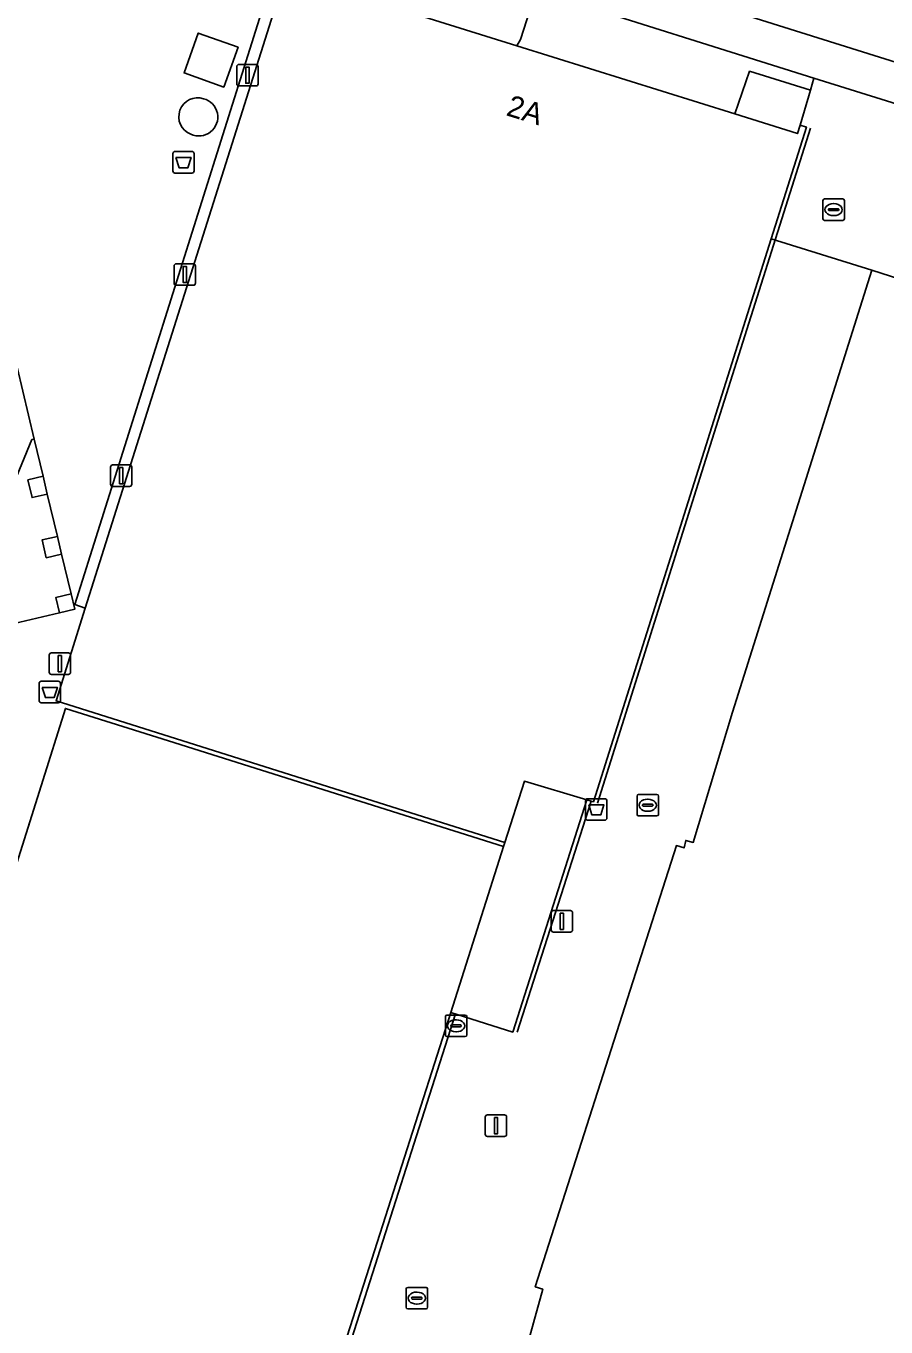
# Model space of a CAD drawing. Extents: x 160675 to 161153, y 383241 to 383714.
# Drawn here: x 161053 to 161093, y 383407.9 to 383468.4 of the extents above; entities that cross this region are included whole.
import ezdxf

# ---------------------------------------------------------------- set-up
doc = ezdxf.new("R2010")
doc.units = 0
for name, color, linetype in [('IMGEO_Afvalbak', 7, 'Continuous'), ('IMGEO_Fietspad_gesloten', 7, 'Continuous'), ('IMGEO_Grasland_overig', 7, 'Continuous'), ('IMGEO_Kolk', 7, 'Continuous'), ('IMGEO_Lichtmast', 7, 'Continuous'), ('IMGEO_Lijnafwatering', 7, 'Continuous'), ('IMGEO_Pand', 7, 'Continuous'), ('IMGEO_Pand_nummerreeks', 7, 'Continuous'), ('IMGEO_Pand_overbouw', 7, 'Continuous'), ('IMGEO_Rijbaan_lokaal_open', 7, 'Continuous'), ('IMGEO_Rioolput', 7, 'Continuous'), ('IMGEO_Terreindeel_open', 7, 'Continuous'), ('IMGEO_Voetgangersgebied_open', 7, 'Continuous'), ('IMGEO_Voetpad_gesloten', 7, 'Continuous'), ('IMGEO_Voetpad_open', 7, 'Continuous')]:
    doc.layers.add(name, color=color, linetype=linetype)

msp = doc.modelspace()

# ---------------------------------------------------------------- linework, layer by layer
at = {"layer": 'IMGEO_Afvalbak'}
for p, q in [((161059.823, 383461.628), (161059.823, 383462.428)), ((161059.823, 383462.428), (161059.823, 383461.628)), ((161059.923, 383462.528), (161060.713, 383462.528)), ((161060.713, 383462.528), (161059.923, 383462.528)), ((161060.813, 383462.428), (161060.813, 383461.628)), ((161060.813, 383461.628), (161060.813, 383462.428)), ((161060.713, 383461.528), (161059.923, 383461.528)), ((161059.923, 383461.528), (161060.713, 383461.528)), ((161053.609, 383436.998), (161053.609, 383437.798)), ((161053.609, 383437.798), (161053.609, 383436.998)), ((161053.709, 383437.898), (161054.499, 383437.898)), ((161054.499, 383437.898), (161053.709, 383437.898)), ((161054.599, 383437.798), (161054.599, 383436.998)), ((161054.599, 383436.998), (161054.599, 383437.798)), ((161054.499, 383436.898), (161053.709, 383436.898)), ((161053.709, 383436.898), (161054.499, 383436.898)), ((161079.007, 383431.541), (161079.007, 383432.341)), ((161079.007, 383432.341), (161079.007, 383431.541)), ((161079.107, 383432.441), (161079.897, 383432.441)), ((161079.897, 383432.441), (161079.107, 383432.441)), ((161079.997, 383432.341), (161079.997, 383431.541)), ((161079.997, 383431.541), (161079.997, 383432.341)), ((161079.897, 383431.441), (161079.107, 383431.441)), ((161079.107, 383431.441), (161079.897, 383431.441))]:
    msp.add_line(p, q, dxfattribs=at)
for points in [[(161059.966, 383462.242), (161060.67, 383462.242), (161060.521, 383461.772), (161060.115, 383461.772), (161059.966, 383462.242)], [(161053.752, 383437.612), (161054.456, 383437.612), (161054.307, 383437.142), (161053.901, 383437.142), (161053.752, 383437.612)], [(161079.15, 383432.155), (161079.854, 383432.155), (161079.705, 383431.685), (161079.299, 383431.685), (161079.15, 383432.155)]]:
    msp.add_lwpolyline(points, dxfattribs=at)
for centre, start, end in [((161059.923, 383462.428), 90, 180), ((161059.923, 383462.428), 90, 180), ((161060.713, 383462.428), 0, 90), ((161060.713, 383462.428), 360, 90), ((161059.923, 383461.628), 180, 270), ((161059.923, 383461.628), 180, 270), ((161060.713, 383461.628), 270, 0), ((161060.713, 383461.628), 270, 0), ((161053.709, 383437.798), 90, 180), ((161053.709, 383437.798), 90, 180), ((161054.499, 383437.798), 0, 90), ((161054.499, 383437.798), 360, 90), ((161053.709, 383436.998), 180, 270), ((161053.709, 383436.998), 180, 270), ((161054.499, 383436.998), 270, 0), ((161054.499, 383436.998), 270, 0), ((161079.107, 383432.341), 90, 180), ((161079.107, 383432.341), 90, 180), ((161079.897, 383432.341), 0, 90), ((161079.897, 383432.341), 360, 90), ((161079.107, 383431.541), 180, 270), ((161079.107, 383431.541), 180, 270), ((161079.897, 383431.541), 270, 0), ((161079.897, 383431.541), 270, 0)]:
    msp.add_arc(centre, 0.1, start, end, dxfattribs=at)
at = {"layer": 'IMGEO_Fietspad_gesloten'}
msp.add_lwpolyline([(161117.721, 383459.056), (161117.222, 383459.213), (161077.255, 383471.761), (161076.702, 383470.014), (161089.617, 383465.938), (161116.681, 383457.491), (161117.138, 383457.349)], dxfattribs=at)
msp.add_lwpolyline([(161089.617, 383465.938), (161076.702, 383470.014), (161075.979, 383467.73), (161075.812, 383467.442), (161085.936, 383464.272), (161086.624, 383466.255), (161089.451, 383465.38)], close=True, dxfattribs=at)
at = {"layer": 'IMGEO_Grasland_overig'}
msp.add_lwpolyline([(161065.07, 383470.806), (161064.564, 383470.995), (161055.274, 383441.468), (161055.753, 383441.293)], close=True, dxfattribs=at)
at = {"layer": 'IMGEO_Kolk'}
for p, q in [((161072.487, 383421.458), (161072.487, 383422.31)), ((161072.562, 383422.384), (161073.414, 383422.384)), ((161072.975, 383422.164), (161073, 383422.164)), ((161073.488, 383422.31), (161073.488, 383421.458)), ((161072.746, 383421.878), (161072.746, 383421.89)), ((161073.184, 383421.841), (161072.786, 383421.841)), ((161072.789, 383421.927), (161073.187, 383421.927)), ((161072.998, 383421.604), (161072.973, 383421.604)), ((161073.23, 383421.89), (161073.23, 383421.878)), ((161073.414, 383421.384), (161072.562, 383421.384))]:
    msp.add_line(p, q, dxfattribs=at)
for points in [[(161072.487, 383421.458), (161072.487, 383422.31)], [(161072.562, 383422.384), (161073.414, 383422.384)], [(161073.488, 383422.31), (161073.488, 383421.458)], [(161073.414, 383421.384), (161072.562, 383421.384)]]:
    msp.add_lwpolyline(points, dxfattribs=at)
for centre, radius, start, end in [((161072.564, 383422.308), 0.0765, 91.55205, 178.44795), ((161072.564, 383422.308), 0.0765, 91.55205, 178.44795), ((161073.412, 383422.308), 0.0765, 1.55205, 88.44795), ((161073.412, 383422.308), 0.0765, 1.55205, 88.44795), ((161072.564, 383421.46), 0.0765, 181.55205, 268.44795), ((161072.564, 383421.46), 0.0765, 181.55205, 268.44795), ((161072.786, 383421.887), 0.0403, 85.87752, 175.75265), ((161072.783, 383421.877), 0.0366, 178.93798, 274.71019), ((161073.187, 383421.884), 0.043, 264.86636, 352.45326), ((161073.191, 383421.889), 0.0386, 1.73085, 96.63898), ((161073.412, 383421.46), 0.0765, 271.55205, 358.44795), ((161073.412, 383421.46), 0.0765, 271.55205, 358.44795)]:
    msp.add_arc(centre, radius, start, end, dxfattribs=at)
for centre, major_axis, ratio, start_param, end_param in [((161072.974, 383421.884), (-0.387, 0.002), 0.722429, 4.712389, 7.853982), ((161072.999, 383421.884), (-0.39, 0.002), 0.717154, 1.570796, 4.712389)]:
    msp.add_ellipse(centre, major_axis=major_axis, ratio=ratio, start_param=start_param, end_param=end_param, dxfattribs=at)
at = {"layer": 'IMGEO_Lichtmast'}
for p, q in [((161062.794, 383465.673), (161062.794, 383466.473)), ((161062.794, 383466.473), (161062.794, 383465.673)), ((161062.894, 383466.573), (161063.684, 383466.573)), ((161063.684, 383466.573), (161062.894, 383466.573)), ((161063.784, 383466.473), (161063.784, 383465.673)), ((161063.784, 383465.673), (161063.784, 383466.473)), ((161063.684, 383465.573), (161062.894, 383465.573)), ((161062.894, 383465.573), (161063.684, 383465.573)), ((161059.883, 383456.407), (161059.883, 383457.207)), ((161059.883, 383457.207), (161059.883, 383456.407)), ((161059.983, 383457.307), (161060.773, 383457.307)), ((161060.773, 383457.307), (161059.983, 383457.307)), ((161060.873, 383457.207), (161060.873, 383456.407)), ((161060.873, 383456.407), (161060.873, 383457.207)), ((161060.773, 383456.307), (161059.983, 383456.307)), ((161059.983, 383456.307), (161060.773, 383456.307)), ((161056.926, 383447.056), (161056.926, 383447.856)), ((161056.926, 383447.856), (161056.926, 383447.056)), ((161057.026, 383447.956), (161057.816, 383447.956)), ((161057.816, 383447.956), (161057.026, 383447.956)), ((161057.916, 383447.856), (161057.916, 383447.056)), ((161057.916, 383447.056), (161057.916, 383447.856)), ((161057.816, 383446.956), (161057.026, 383446.956)), ((161057.026, 383446.956), (161057.816, 383446.956)), ((161054.078, 383438.318), (161054.078, 383439.118)), ((161054.078, 383439.118), (161054.078, 383438.318)), ((161054.178, 383439.218), (161054.968, 383439.218)), ((161054.968, 383439.218), (161054.178, 383439.218)), ((161055.068, 383439.118), (161055.068, 383438.318)), ((161055.068, 383438.318), (161055.068, 383439.118)), ((161054.968, 383438.218), (161054.178, 383438.218)), ((161054.178, 383438.218), (161054.968, 383438.218)), ((161077.406, 383426.343), (161077.406, 383427.143)), ((161077.406, 383427.143), (161077.406, 383426.343)), ((161077.506, 383427.243), (161078.296, 383427.243)), ((161078.296, 383427.243), (161077.506, 383427.243)), ((161078.396, 383427.143), (161078.396, 383426.343)), ((161078.396, 383426.343), (161078.396, 383427.143)), ((161078.296, 383426.243), (161077.506, 383426.243)), ((161077.506, 383426.243), (161078.296, 383426.243)), ((161074.345, 383416.84), (161074.345, 383417.64)), ((161074.345, 383417.64), (161074.345, 383416.84)), ((161074.445, 383417.74), (161075.235, 383417.74)), ((161075.235, 383417.74), (161074.445, 383417.74)), ((161075.335, 383417.64), (161075.335, 383416.84)), ((161075.335, 383416.84), (161075.335, 383417.64)), ((161075.235, 383416.74), (161074.445, 383416.74)), ((161074.445, 383416.74), (161075.235, 383416.74))]:
    msp.add_line(p, q, dxfattribs=at)
for points in [[(161063.214, 383466.448), (161063.364, 383466.448), (161063.364, 383465.698), (161063.214, 383465.698), (161063.214, 383466.448)], [(161060.303, 383457.182), (161060.453, 383457.182), (161060.453, 383456.432), (161060.303, 383456.432), (161060.303, 383457.182)], [(161057.346, 383447.831), (161057.496, 383447.831), (161057.496, 383447.081), (161057.346, 383447.081), (161057.346, 383447.831)], [(161054.498, 383439.093), (161054.648, 383439.093), (161054.648, 383438.343), (161054.498, 383438.343), (161054.498, 383439.093)], [(161077.826, 383427.118), (161077.976, 383427.118), (161077.976, 383426.368), (161077.826, 383426.368), (161077.826, 383427.118)], [(161074.765, 383417.615), (161074.915, 383417.615), (161074.915, 383416.865), (161074.765, 383416.865), (161074.765, 383417.615)]]:
    msp.add_lwpolyline(points, dxfattribs=at)
for centre, start, end in [((161062.894, 383466.473), 90, 180), ((161062.894, 383466.473), 90, 180), ((161063.684, 383466.473), 0, 90), ((161063.684, 383466.473), 360, 90), ((161062.894, 383465.673), 180, 270), ((161062.894, 383465.673), 180, 270), ((161063.684, 383465.673), 270, 0), ((161063.684, 383465.673), 270, 0), ((161059.983, 383457.207), 90, 180), ((161059.983, 383457.207), 90, 180), ((161060.773, 383457.207), 0, 90), ((161060.773, 383457.207), 360, 90), ((161059.983, 383456.407), 180, 270), ((161059.983, 383456.407), 180, 270), ((161060.773, 383456.407), 270, 0), ((161060.773, 383456.407), 270, 0), ((161057.026, 383447.856), 90, 180), ((161057.026, 383447.856), 90, 180), ((161057.816, 383447.856), 0, 90), ((161057.816, 383447.856), 360, 90), ((161057.026, 383447.056), 180, 270), ((161057.026, 383447.056), 180, 270), ((161057.816, 383447.056), 270, 0), ((161057.816, 383447.056), 270, 0), ((161054.178, 383439.118), 90, 180), ((161054.178, 383439.118), 90, 180), ((161054.968, 383439.118), 0, 90), ((161054.968, 383439.118), 360, 90), ((161054.178, 383438.318), 180, 270), ((161054.178, 383438.318), 180, 270), ((161054.968, 383438.318), 270, 0), ((161054.968, 383438.318), 270, 0), ((161077.506, 383427.143), 90, 180), ((161077.506, 383427.143), 90, 180), ((161078.296, 383427.143), 0, 90), ((161078.296, 383427.143), 360, 90), ((161077.506, 383426.343), 180, 270), ((161077.506, 383426.343), 180, 270), ((161078.296, 383426.343), 270, 0), ((161078.296, 383426.343), 270, 0), ((161074.445, 383417.64), 90, 180), ((161074.445, 383417.64), 90, 180), ((161075.235, 383417.64), 0, 90), ((161075.235, 383417.64), 360, 90), ((161074.445, 383416.84), 180, 270), ((161074.445, 383416.84), 180, 270), ((161075.235, 383416.84), 270, 0), ((161075.235, 383416.84), 270, 0)]:
    msp.add_arc(centre, 0.1, start, end, dxfattribs=at)
at = {"layer": 'IMGEO_Lijnafwatering'}
for points in [[(161084.506, 383447.923), (161089.456, 383463.605)], [(161079.556, 383432.24), (161084.506, 383447.923)], [(161059.617, 383435.13), (161054.833, 383436.641), (161051.429, 383425.846)], [(161075.195, 383430.212), (161059.617, 383435.13)], [(161075.832, 383421.583), (161079.256, 383432.332)], [(161066.777, 383403.1), (161068.012, 383406.968), (161072.955, 383422.439)]]:
    msp.add_lwpolyline(points, dxfattribs=at)
at = {"layer": 'IMGEO_Pand'}
for points in [[(161087.625, 383458.471), (161089.265, 383463.665), (161088.969, 383463.756), (161088.845, 383463.361), (161085.936, 383464.272), (161075.812, 383467.442), (161065.769, 383470.587), (161065.355, 383470.717), (161065.07, 383470.806), (161055.753, 383441.293), (161054.395, 383436.989), (161054.702, 383436.892), (161075.255, 383430.401), (161076.159, 383433.252), (161079.064, 383432.389), (161079.256, 383432.332), (161079.365, 383432.3)], [(161053.796, 383447.429), (161053.086, 383447.264), (161053.279, 383446.436), (161053.989, 383446.602)], [(161054.457, 383444.637), (161053.75, 383444.473), (161053.943, 383443.64), (161054.651, 383443.805)], [(161055.101, 383441.964), (161054.39, 383441.801), (161054.553, 383441.089), (161055.264, 383441.251)]]:
    msp.add_lwpolyline(points, close=True, dxfattribs=at)
for points in [[(161099.585, 383454.678), (161092.303, 383457.008), (161085.837, 383436.463), (161084.008, 383430.41), (161083.662, 383430.505), (161083.581, 383430.155), (161083.222, 383430.26), (161076.661, 383409.753), (161077.013, 383409.636), (161075.201, 383403.108)], [(161049.507, 383440.018), (161053.275, 383449.133), (161053.38, 383449.156), (161051.779, 383455.847)]]:
    msp.add_lwpolyline(points, dxfattribs=at)
at = {"layer": 'IMGEO_Pand_overbouw'}
msp.add_lwpolyline([(161055.101, 383441.964), (161054.651, 383443.805), (161053.943, 383443.64), (161053.75, 383444.473), (161054.457, 383444.637), (161053.989, 383446.602), (161053.279, 383446.436), (161053.086, 383447.264), (161053.796, 383447.429), (161053.38, 383449.156), (161053.275, 383449.133), (161049.507, 383440.018), (161049.535, 383439.901), (161054.553, 383441.089), (161054.39, 383441.801)], close=True, dxfattribs=at)
at = {"layer": 'IMGEO_Rijbaan_lokaal_open'}
msp.add_lwpolyline([(161066.803, 383474.038), (161066.557, 383473.216), (161076.702, 383470.014), (161077.255, 383471.761), (161117.222, 383459.213), (161117.721, 383459.056)], dxfattribs=at)
msp.add_lwpolyline([(161075.812, 383467.442), (161075.979, 383467.73), (161076.702, 383470.014), (161066.557, 383473.216), (161065.997, 383471.348), (161065.769, 383470.587)], close=True, dxfattribs=at)
at = {"layer": 'IMGEO_Rioolput'}
for p, q in [((161090.03, 383459.399), (161090.03, 383460.251)), ((161090.105, 383460.325), (161090.957, 383460.325)), ((161091.031, 383460.251), (161091.031, 383459.399)), ((161090.289, 383459.819), (161090.289, 383459.831)), ((161090.727, 383459.782), (161090.329, 383459.782)), ((161090.332, 383459.868), (161090.73, 383459.868)), ((161090.541, 383459.545), (161090.516, 383459.545)), ((161090.518, 383460.105), (161090.543, 383460.105)), ((161090.773, 383459.831), (161090.773, 383459.819)), ((161090.957, 383459.325), (161090.105, 383459.325)), ((161081.394, 383431.712), (161081.394, 383432.564)), ((161081.469, 383432.638), (161082.321, 383432.638)), ((161081.882, 383432.418), (161081.907, 383432.418)), ((161082.395, 383432.564), (161082.395, 383431.712)), ((161081.653, 383432.132), (161081.653, 383432.144)), ((161082.091, 383432.095), (161081.693, 383432.095)), ((161081.696, 383432.181), (161082.094, 383432.181)), ((161081.905, 383431.858), (161081.88, 383431.858)), ((161082.137, 383432.144), (161082.137, 383432.132)), ((161082.321, 383431.638), (161081.469, 383431.638)), ((161070.661, 383408.798), (161070.661, 383409.65)), ((161070.736, 383409.724), (161071.588, 383409.724)), ((161071.149, 383409.504), (161071.174, 383409.504)), ((161071.662, 383409.65), (161071.662, 383408.798)), ((161071.588, 383408.724), (161070.736, 383408.724)), ((161070.92, 383409.218), (161070.92, 383409.23)), ((161071.358, 383409.181), (161070.96, 383409.181)), ((161070.963, 383409.267), (161071.361, 383409.267)), ((161071.172, 383408.944), (161071.147, 383408.944)), ((161071.404, 383409.23), (161071.404, 383409.218))]:
    msp.add_line(p, q, dxfattribs=at)
for points in [[(161090.03, 383459.399), (161090.03, 383460.251)], [(161090.105, 383460.325), (161090.957, 383460.325)], [(161091.031, 383460.251), (161091.031, 383459.399)], [(161090.957, 383459.325), (161090.105, 383459.325)], [(161081.394, 383431.712), (161081.394, 383432.564)], [(161081.469, 383432.638), (161082.321, 383432.638)], [(161082.395, 383432.564), (161082.395, 383431.712)], [(161082.321, 383431.638), (161081.469, 383431.638)], [(161070.661, 383408.798), (161070.661, 383409.65)], [(161070.736, 383409.724), (161071.588, 383409.724)], [(161071.662, 383409.65), (161071.662, 383408.798)], [(161071.588, 383408.724), (161070.736, 383408.724)]]:
    msp.add_lwpolyline(points, dxfattribs=at)
for centre, radius, start, end in [((161090.107, 383460.249), 0.0765, 91.55205, 178.44795), ((161090.107, 383460.249), 0.0765, 91.55205, 178.44795), ((161090.955, 383460.249), 0.0765, 1.55205, 88.44795), ((161090.955, 383460.249), 0.0765, 1.55205, 88.44795), ((161090.329, 383459.828), 0.0403, 85.87752, 175.75265), ((161090.326, 383459.818), 0.0366, 178.93798, 274.71019), ((161090.73, 383459.825), 0.043, 264.86636, 352.45326), ((161090.734, 383459.83), 0.0386, 1.73085, 96.63898), ((161090.107, 383459.401), 0.0765, 181.55205, 268.44795), ((161090.107, 383459.401), 0.0765, 181.55205, 268.44795), ((161090.955, 383459.401), 0.0765, 271.55205, 358.44795), ((161090.955, 383459.401), 0.0765, 271.55205, 358.44795), ((161081.471, 383432.562), 0.0765, 91.55205, 178.44795), ((161081.471, 383432.562), 0.0765, 91.55205, 178.44795), ((161082.319, 383432.562), 0.0765, 1.55205, 88.44795), ((161082.319, 383432.562), 0.0765, 1.55205, 88.44795), ((161081.471, 383431.714), 0.0765, 181.55205, 268.44795), ((161081.471, 383431.714), 0.0765, 181.55205, 268.44795), ((161081.693, 383432.141), 0.0403, 85.87752, 175.75265), ((161081.69, 383432.131), 0.0366, 178.93798, 274.71019), ((161082.094, 383432.138), 0.043, 264.86636, 352.45326), ((161082.098, 383432.143), 0.0386, 1.73085, 96.63898), ((161082.319, 383431.714), 0.0765, 271.55205, 358.44795), ((161082.319, 383431.714), 0.0765, 271.55205, 358.44795), ((161070.738, 383409.648), 0.0765, 91.55205, 178.44795), ((161070.738, 383409.648), 0.0765, 91.55205, 178.44795), ((161071.586, 383409.648), 0.0765, 1.55205, 88.44795), ((161071.586, 383409.648), 0.0765, 1.55205, 88.44795), ((161070.738, 383408.8), 0.0765, 181.55205, 268.44795), ((161070.738, 383408.8), 0.0765, 181.55205, 268.44795), ((161070.96, 383409.227), 0.0403, 85.87752, 175.75265), ((161070.957, 383409.217), 0.0366, 178.93798, 274.71019), ((161071.361, 383409.224), 0.043, 264.86636, 352.45326), ((161071.365, 383409.229), 0.0386, 1.73085, 96.63898), ((161071.586, 383408.8), 0.0765, 271.55205, 358.44795), ((161071.586, 383408.8), 0.0765, 271.55205, 358.44795)]:
    msp.add_arc(centre, radius, start, end, dxfattribs=at)
for centre, major_axis, ratio, start_param, end_param in [((161090.517, 383459.825), (-0.387, 0.002), 0.722429, 4.712389, 7.853982), ((161090.542, 383459.825), (-0.39, 0.002), 0.717154, 1.570796, 4.712389), ((161081.881, 383432.138), (-0.387, 0.002), 0.722429, 4.712389, 7.853982), ((161081.906, 383432.138), (-0.39, 0.002), 0.717154, 1.570796, 4.712389), ((161071.148, 383409.224), (-0.387, 0.002), 0.722429, 4.712389, 7.853982), ((161071.173, 383409.224), (-0.39, 0.002), 0.717154, 1.570796, 4.712389)]:
    msp.add_ellipse(centre, major_axis=major_axis, ratio=ratio, start_param=start_param, end_param=end_param, dxfattribs=at)
at = {"layer": 'IMGEO_Terreindeel_open'}
msp.add_lwpolyline([(161062.192, 383465.522), (161062.855, 383467.373), (161061.005, 383468.035), (161060.342, 383466.184)], close=True, dxfattribs=at)
for centre, radius, start, end in [((161060.977, 383464.148), 0.877, 71.68188, 248.36866), ((161061.03, 383464.129), 0.881, 244.68747, 75.36307)]:
    msp.add_arc(centre, radius, start, end, dxfattribs=at)
at = {"layer": 'IMGEO_Voetgangersgebied_open'}
for points in [[(161116.681, 383457.491), (161089.617, 383465.938), (161089.451, 383465.38), (161088.969, 383463.756), (161089.265, 383463.665), (161087.625, 383458.471), (161092.303, 383457.008), (161099.585, 383454.678)], [(161075.201, 383403.108), (161077.013, 383409.636), (161076.661, 383409.753), (161083.222, 383430.26), (161083.581, 383430.155), (161083.662, 383430.505), (161084.008, 383430.41), (161085.837, 383436.463), (161092.303, 383457.008), (161087.625, 383458.471), (161079.365, 383432.3), (161079.256, 383432.332), (161079.064, 383432.389), (161075.619, 383421.592), (161072.736, 383422.509), (161061.981, 383388.875)]]:
    msp.add_lwpolyline(points, dxfattribs=at)
at = {"layer": 'IMGEO_Voetpad_gesloten'}
for points in [[(161085.936, 383464.272), (161088.845, 383463.361), (161088.969, 383463.756), (161089.451, 383465.38), (161086.624, 383466.255)], [(161076.159, 383433.252), (161075.255, 383430.401), (161075.195, 383430.212), (161072.736, 383422.509), (161075.619, 383421.592), (161079.064, 383432.389)]]:
    msp.add_lwpolyline(points, close=True, dxfattribs=at)
at = {"layer": 'IMGEO_Voetpad_open'}
for points in [[(161061.981, 383388.875), (161072.736, 383422.509), (161075.195, 383430.212), (161075.255, 383430.401), (161054.702, 383436.892), (161054.395, 383436.989), (161055.753, 383441.293), (161055.274, 383441.468), (161064.564, 383470.995), (161065.07, 383470.806), (161066.152, 383474.253)], [(161051.779, 383455.847), (161053.38, 383449.156), (161053.796, 383447.429), (161053.989, 383446.602), (161054.457, 383444.637), (161054.651, 383443.805), (161055.101, 383441.964), (161055.264, 383441.251), (161054.553, 383441.089), (161049.535, 383439.901)]]:
    msp.add_lwpolyline(points, dxfattribs=at)
for points in [[(161060.342, 383466.184), (161061.005, 383468.035), (161062.855, 383467.373), (161062.192, 383465.522)], [(161053.38, 383449.156), (161053.275, 383449.133), (161049.507, 383440.018), (161049.535, 383439.901), (161054.553, 383441.089), (161054.39, 383441.801), (161055.101, 383441.964), (161054.651, 383443.805), (161053.943, 383443.64), (161053.75, 383444.473), (161054.457, 383444.637), (161053.989, 383446.602), (161053.279, 383446.436), (161053.086, 383447.264), (161053.796, 383447.429)]]:
    msp.add_lwpolyline(points, close=True, dxfattribs=at)
for centre, radius, start, end in [((161060.977, 383464.148), 0.877, 71.68188, 248.36866), ((161061.03, 383464.129), 0.881, 244.68747, 75.36307)]:
    msp.add_arc(centre, radius, start, end, dxfattribs=at)

# ---------------------------------------------------------------- texts
at = {"layer": 'IMGEO_Pand_nummerreeks'}
msp.add_text('2A', height=1, rotation=342.75397, dxfattribs=at).set_placement((161075.269, 383464.221))

doc.saveas('drawing.dxf')
